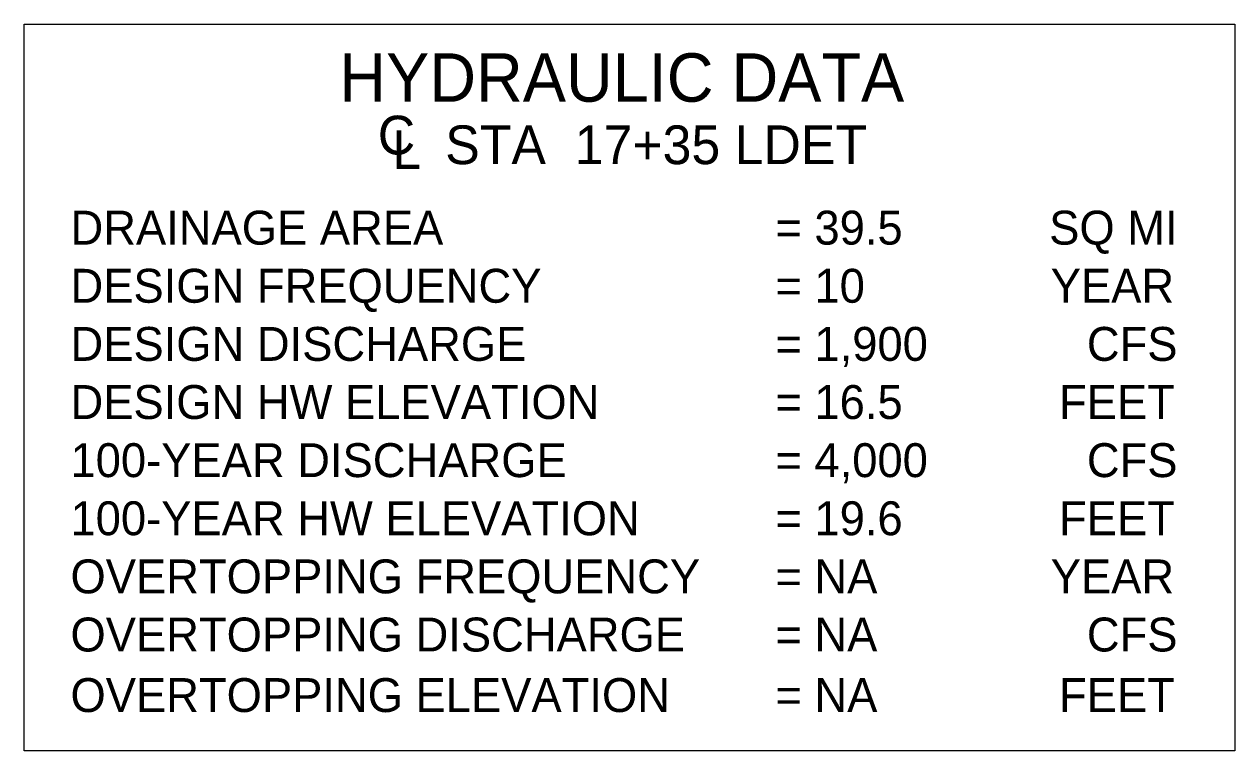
# Model space of a CAD drawing. Extents: x 0.06 to 3.35, y -0.26 to 1.73.
# Drawn here: x 1.2834 to 1.5834, y 1.4094 to 1.5894 of the extents above; entities that cross this region are included whole.
import ezdxf

# ---------------------------------------------------------------- set-up
doc = ezdxf.new("R2010")
doc.units = 0
doc.layers.add('Draft_Generic_Leader', color=7, linetype='Continuous')
doc.layers.add('P_NCDOT_Vertical_Profile_Strip_Grade', color=7, linetype='Continuous')

msp = doc.modelspace()

# ---------------------------------------------------------------- linework, layer by layer
at = {"layer": 'P_NCDOT_Vertical_Profile_Strip_Grade'}
msp.add_lwpolyline([(1.28337, 1.58937), (1.58337, 1.58937), (1.58337, 1.40937), (1.28337, 1.40937)], close=True, dxfattribs=at)

# ---------------------------------------------------------------- texts
at = {"layer": 'Draft_Generic_Leader'}
for s, height, p in [('HYDRAULIC DATA', 0.012, (1.36146, 1.57017)), ('C', 0.0096, (1.37099, 1.5571)), ('L', 0.0096, (1.37459, 1.5535)), ('STA  17+35 LDET', 0.0096, (1.3877, 1.5547)), ('DRAINAGE AREA', 0.0084, (1.29484, 1.53477)), ('= 39.5', 0.0084, (1.46952, 1.53477)), ('SQ MI', 0.0084, (1.53737, 1.53477)), ('DESIGN FREQUENCY', 0.0084, (1.29484, 1.52037)), ('= 10', 0.0084, (1.46952, 1.52037)), ('YEAR', 0.0084, (1.53776, 1.52037)), ('DESIGN DISCHARGE', 0.0084, (1.29484, 1.50597)), ('= 1,900', 0.0084, (1.46952, 1.50597)), ('CFS', 0.0084, (1.54671, 1.50597)), ('DESIGN HW ELEVATION', 0.0084, (1.29484, 1.49157)), ('= 16.5', 0.0084, (1.46952, 1.49157)), ('FEET', 0.0084, (1.53981, 1.49157)), ('100-YEAR DISCHARGE', 0.0084, (1.29484, 1.47717)), ('= 4,000', 0.0084, (1.46952, 1.47717)), ('CFS', 0.0084, (1.54671, 1.47717)), ('100-YEAR HW ELEVATION', 0.0084, (1.29484, 1.46277)), ('= 19.6', 0.0084, (1.46952, 1.46277)), ('FEET', 0.0084, (1.53981, 1.46277)), ('OVERTOPPING FREQUENCY', 0.0084, (1.29484, 1.44837)), ('= NA', 0.0084, (1.46952, 1.44837)), ('YEAR', 0.0084, (1.53776, 1.44837)), ('OVERTOPPING DISCHARGE', 0.0084, (1.29484, 1.43397)), ('= NA', 0.0084, (1.46952, 1.43397)), ('CFS', 0.0084, (1.54671, 1.43397)), ('OVERTOPPING ELEVATION', 0.0084, (1.29484, 1.41897)), ('= NA', 0.0084, (1.46952, 1.41897)), ('FEET', 0.0084, (1.53981, 1.41897))]:
    msp.add_text(s, height=height, dxfattribs=at).set_placement(p)

doc.saveas('drawing.dxf')
